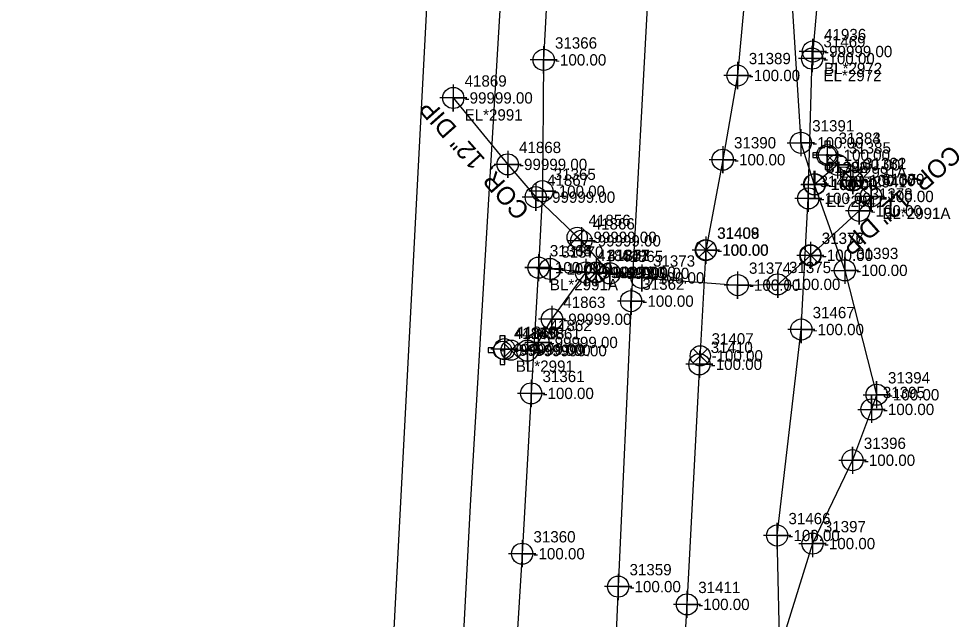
# Model space of a CAD drawing. Extents: x 2083698 to 2094313, y 743246 to 752873.
# Drawn here: x 2093555 to 2093762.7, y 745136.4 to 745269.1 of the extents above; entities that cross this region are included whole.
import ezdxf

# ---------------------------------------------------------------- set-up
doc = ezdxf.new("R2010")
doc.units = 0
for name, color, linetype in [('COGO Default Chain', 7, 'Continuous'), ('COGO Default Curve', 7, 'Continuous'), ('COGO Default Point Number', 7, 'Continuous'), ('Exist Property Line', 7, 'Continuous'), ('Exist Right of Way Easement Line', 7, 'Continuous'), ('Exist Right of Way Easement Line Leader', 7, 'Continuous'), ('Exist Right of Way Easement Line Text', 7, 'Continuous'), ('Exist Right of Way Line', 7, 'Continuous'), ('Exist Right of Way Line Leader', 7, 'Continuous'), ('Exist Right of Way Line Text', 7, 'Continuous'), ('Exist Right of Way Width CELL', 7, 'Continuous'), ('Exist Roads EOP', 7, 'Continuous'), ('Exist Roads EOP Leader', 7, 'Continuous'), ('Exist Roads EOP Text', 7, 'Continuous'), ('Exist Utilities Gas UG Line SUE LOS B', 7, 'Continuous'), ('Exist Utilities Power UG Cable SUE LOS C', 7, 'Continuous'), ('Exist Utilities Telephone UG Conduit SUE LOS B', 7, 'Continuous'), ('Exist Utilities Telephone UG Conduit SUE LOS D', 7, 'Continuous'), ('Exist Utilities Water UG Line SUE LOS B', 7, 'Continuous'), ('Exist Utilities Water UG Line SUE LOS B Text', 7, 'Continuous'), ('Old_Level_20', 7, 'Continuous'), ('Raster_Level_1', 7, 'Continuous'), ('Scratch_Level_2', 7, 'Continuous'), ('Scratch_Level_3', 7, 'Continuous')]:
    doc.layers.add(name, color=color, linetype=linetype)

msp = doc.modelspace()

# ---------------------------------------------------------------- linework, layer by layer
at = {"layer": 'COGO Default Curve'}
for points in [[(2093724.76, 745241.69), (2093730.76, 745241.69), (2093727.76, 745241.69), (2093727.76, 745244.69), (2093727.76, 745238.69)], [(2093732.85, 745236.81), (2093738.85, 745236.81), (2093735.85, 745236.81), (2093735.85, 745239.81), (2093735.85, 745233.81)], [(2093727.72, 745232.48), (2093733.72, 745232.48), (2093730.72, 745232.48), (2093730.72, 745235.48), (2093730.72, 745229.48)], [(2093727.85, 745232.5), (2093733.85, 745232.5), (2093730.85, 745232.5), (2093730.85, 745235.5), (2093730.85, 745229.5)], [(2093734.48, 745213.48), (2093740.48, 745213.48), (2093737.48, 745213.48), (2093737.48, 745216.48), (2093737.48, 745210.48)], [(2093741.49, 745185.98), (2093747.49, 745185.98), (2093744.49, 745185.98), (2093744.49, 745188.98), (2093744.49, 745182.98)], [(2093740.37, 745182.74), (2093746.37, 745182.74), (2093743.37, 745182.74), (2093743.37, 745185.74), (2093743.37, 745179.74)], [(2093736.16, 745171.5), (2093742.16, 745171.5), (2093739.16, 745171.5), (2093739.16, 745174.5), (2093739.16, 745168.5)], [(2093727.33, 745153.07), (2093733.33, 745153.07), (2093730.33, 745153.07), (2093730.33, 745156.07), (2093730.33, 745150.07)]]:
    msp.add_lwpolyline(points, dxfattribs=at)
for centre in [(2093727.76, 745241.69), (2093735.85, 745236.81), (2093730.72, 745232.48), (2093730.85, 745232.5), (2093737.48, 745213.48), (2093744.49, 745185.98), (2093743.37, 745182.74), (2093739.16, 745171.5), (2093730.33, 745153.07)]:
    msp.add_circle(centre, 2.34, dxfattribs=at)
at = {"layer": 'COGO Default Point Number'}
for points in [[(2093670.94, 745263.01), (2093670.94, 745257.01), (2093670.94, 745260.01), (2093673.94, 745260.01), (2093667.94, 745260.01)], [(2093713.75, 745259.56), (2093713.75, 745253.56), (2093713.75, 745256.56), (2093716.75, 745256.56), (2093710.75, 745256.56)], [(2093650.98, 745254.6), (2093650.98, 745248.6), (2093650.98, 745251.6), (2093653.98, 745251.6), (2093647.98, 745251.6)], [(2093733.6, 745241.94), (2093733.6, 745235.94), (2093733.6, 745238.94), (2093736.6, 745238.94), (2093730.6, 745238.94)], [(2093663, 745239.91), (2093663, 745233.91), (2093663, 745236.91), (2093666, 745236.91), (2093660, 745236.91)], [(2093710.49, 745240.94), (2093710.49, 745234.94), (2093710.49, 745237.94), (2093713.49, 745237.94), (2093707.49, 745237.94)], [(2093739.21, 745236.32), (2093739.21, 745230.32), (2093739.21, 745233.32), (2093742.21, 745233.32), (2093736.21, 745233.32)], [(2093670.66, 745233.97), (2093670.66, 745227.97), (2093670.66, 745230.97), (2093673.66, 745230.97), (2093667.66, 745230.97)], [(2093669.19, 745232.67), (2093669.19, 745226.67), (2093669.19, 745229.67), (2093672.19, 745229.67), (2093666.19, 745229.67)], [(2093743.24, 745232.83), (2093743.24, 745226.83), (2093743.24, 745229.83), (2093746.24, 745229.83), (2093740.24, 745229.83)], [(2093743.26, 745232.82), (2093743.26, 745226.82), (2093743.26, 745229.82), (2093746.26, 745229.82), (2093740.26, 745229.82)], [(2093740.64, 745229.63), (2093740.64, 745223.63), (2093740.64, 745226.63), (2093743.64, 745226.63), (2093737.64, 745226.63)], [(2093679.27, 745223.01), (2093679.27, 745217.01), (2093679.27, 745220.01), (2093682.27, 745220.01), (2093676.27, 745220.01)], [(2093706.75, 745220.95), (2093706.75, 745214.95), (2093706.75, 745217.95), (2093709.75, 745217.95), (2093703.75, 745217.95)], [(2093729.86, 745219.8), (2093729.86, 745213.8), (2093729.86, 745216.8), (2093732.86, 745216.8), (2093726.86, 745216.8)], [(2093669.8, 745217.08), (2093669.8, 745211.08), (2093669.8, 745214.08), (2093672.8, 745214.08), (2093666.8, 745214.08)], [(2093669.81, 745217.07), (2093669.81, 745211.07), (2093669.81, 745214.07), (2093672.81, 745214.07), (2093666.81, 745214.07)], [(2093672.35, 745216.79), (2093672.35, 745210.79), (2093672.35, 745213.79), (2093675.35, 745213.79), (2093669.35, 745213.79)], [(2093680.26, 745216.02), (2093680.26, 745210.02), (2093680.26, 745213.02), (2093683.26, 745213.02), (2093677.26, 745213.02)], [(2093682.52, 745216.02), (2093682.52, 745210.02), (2093682.52, 745213.02), (2093685.52, 745213.02), (2093679.52, 745213.02)], [(2093685.55, 745215.82), (2093685.55, 745209.82), (2093685.55, 745212.82), (2093688.55, 745212.82), (2093682.55, 745212.82)], [(2093692.6, 745214.81), (2093692.6, 745208.81), (2093692.6, 745211.81), (2093695.6, 745211.81), (2093689.6, 745211.81)], [(2093713.79, 745213.22), (2093713.79, 745207.22), (2093713.79, 745210.22), (2093716.79, 745210.22), (2093710.79, 745210.22)], [(2093722.64, 745213.38), (2093722.64, 745207.38), (2093722.64, 745210.38), (2093725.64, 745210.38), (2093719.64, 745210.38)], [(2093672.78, 745205.67), (2093672.78, 745199.67), (2093672.78, 745202.67), (2093675.78, 745202.67), (2093669.78, 745202.67)], [(2093669.76, 745200.55), (2093669.76, 745194.55), (2093669.76, 745197.55), (2093672.76, 745197.55), (2093666.76, 745197.55)], [(2093662.29, 745199.05), (2093662.29, 745193.05), (2093662.29, 745196.05), (2093665.29, 745196.05), (2093659.29, 745196.05)], [(2093667.34, 745198.73), (2093667.34, 745192.73), (2093667.34, 745195.73), (2093670.34, 745195.73), (2093664.34, 745195.73)], [(2093705.34, 745195.71), (2093705.34, 745189.71), (2093705.34, 745192.71), (2093708.34, 745192.71), (2093702.34, 745192.71)], [(2093668.19, 745189.28), (2093668.19, 745183.28), (2093668.19, 745186.28), (2093671.19, 745186.28), (2093665.19, 745186.28)], [(2093666.19, 745153.83), (2093666.19, 745147.83), (2093666.19, 745150.83), (2093669.19, 745150.83), (2093663.19, 745150.83)], [(2093702.59, 745142.63), (2093702.59, 745136.63), (2093702.59, 745139.63), (2093705.59, 745139.63), (2093699.59, 745139.63)]]:
    msp.add_lwpolyline(points, dxfattribs=at)
for centre in [(2093670.94, 745260.01), (2093713.75, 745256.56), (2093650.98, 745251.6), (2093710.49, 745237.94), (2093733.6, 745238.94), (2093663, 745236.91), (2093739.21, 745233.32), (2093669.19, 745229.67), (2093670.66, 745230.97), (2093743.24, 745229.83), (2093743.26, 745229.82), (2093740.64, 745226.63), (2093679.27, 745220.01), (2093706.75, 745217.95), (2093729.86, 745216.8), (2093669.8, 745214.08), (2093669.81, 745214.07), (2093672.35, 745213.79), (2093680.26, 745213.02), (2093682.52, 745213.02), (2093685.55, 745212.82), (2093692.6, 745211.81), (2093722.64, 745210.38), (2093713.79, 745210.22), (2093672.78, 745202.67), (2093662.29, 745196.05), (2093667.34, 745195.73), (2093669.76, 745197.55), (2093705.34, 745192.71), (2093668.19, 745186.28), (2093666.19, 745150.83), (2093702.59, 745139.63)]:
    msp.add_circle(centre, 2.34, dxfattribs=at)
at = {"layer": 'Exist Right of Way Line Text'}
for points in [[(2093730.35, 745264.68), (2093730.39, 745258.87), (2093730.37, 745261.87), (2093733.39, 745261.87), (2093727.39, 745261.87)], [(2093730.21, 745263.12), (2093730.24, 745257.3), (2093730.22, 745260.3), (2093733.24, 745260.3), (2093727.24, 745260.3)], [(2093729.36, 745232.2), (2093729.39, 745226.39), (2093729.38, 745229.39), (2093732.39, 745229.39), (2093726.39, 745229.39)], [(2093690.21, 745209.49), (2093690.25, 745203.68), (2093690.23, 745206.68), (2093693.25, 745206.68), (2093687.25, 745206.68)], [(2093727.81, 745203.21), (2093727.85, 745197.4), (2093727.83, 745200.4), (2093730.85, 745200.4), (2093724.85, 745200.4)], [(2093722.48, 745157.68), (2093722.51, 745151.86), (2093722.5, 745154.86), (2093725.51, 745154.86), (2093719.51, 745154.86)], [(2093687.38, 745146.37), (2093687.41, 745140.56), (2093687.39, 745143.56), (2093690.41, 745143.56), (2093684.41, 745143.56)]]:
    msp.add_lwpolyline(points, dxfattribs=at)
for centre in [(2093730.24, 745260.3), (2093730.39, 745261.87), (2093729.39, 745229.39), (2093690.25, 745206.68), (2093727.85, 745200.4), (2093722.51, 745154.86), (2093687.41, 745143.56)]:
    msp.add_circle(centre, 2.34, dxfattribs=at)
at = {"layer": 'Exist Roads EOP'}
for points in [[(2093740.81, 745234.94), (2093737.66, 745231.79), (2093739.24, 745233.36), (2093740.81, 745231.79), (2093737.66, 745234.94)], [(2093679.92, 745222.36), (2093676.77, 745219.21), (2093678.35, 745220.79), (2093679.92, 745219.21), (2093676.77, 745222.36)], [(2093708.4, 745219.55), (2093705.25, 745216.4), (2093706.82, 745217.98), (2093708.4, 745216.4), (2093705.25, 745219.55)], [(2093731.46, 745218.41), (2093728.31, 745215.26), (2093729.88, 745216.83), (2093731.46, 745215.26), (2093728.31, 745218.41)], [(2093684.06, 745214.62), (2093680.91, 745211.47), (2093682.48, 745213.04), (2093684.06, 745211.47), (2093680.91, 745214.62)], [(2093684.15, 745214.63), (2093681, 745211.48), (2093682.57, 745213.06), (2093684.15, 745211.48), (2093681, 745214.63)], [(2093665.31, 745197.4), (2093662.16, 745194.25), (2093663.74, 745195.83), (2093665.31, 745194.25), (2093662.16, 745197.4)], [(2093707.1, 745196.15), (2093703.95, 745193), (2093705.53, 745194.58), (2093707.1, 745193), (2093703.95, 745196.15)]]:
    msp.add_lwpolyline(points, dxfattribs=at)
for centre in [(2093739.24, 745233.36), (2093678.35, 745220.79), (2093706.82, 745217.98), (2093729.88, 745216.83), (2093682.48, 745213.04), (2093682.57, 745213.06), (2093663.74, 745195.83), (2093705.53, 745194.58)]:
    msp.add_circle(centre, 2.23, dxfattribs=at)
at = {"layer": 'Exist Utilities Gas UG Line SUE LOS B'}
msp.add_line((2093735.85, 745236.81), (2093730.85, 745232.5), dxfattribs=at)
msp.add_lwpolyline([(2093725.11, 745283.85), (2093727.76, 745241.69), (2093730.72, 745232.48), (2093737.48, 745213.48), (2093744.49, 745185.98), (2093743.37, 745182.74), (2093739.16, 745171.5), (2093730.33, 745153.07), (2093723.45, 745131.04), (2093716.57, 745100.74), (2093713.22, 745075.27), (2093711.06, 745049.53), (2093708, 745004.83), (2093705.88, 744955.66), (2093705.01, 744921.44), (2093703.7, 744905.03), (2093703.35, 744902.58)], dxfattribs=at)
at = {"layer": 'Exist Utilities Power UG Cable SUE LOS C'}
msp.add_lwpolyline([(2093680.17, 745945.58), (2093662.25, 745598.14), (2093631.4, 745010.86), (2093607.2, 744576.6), (2093577.14, 744030.24)], dxfattribs=at)
at = {"layer": 'Exist Utilities Telephone UG Conduit SUE LOS B'}
for points in [[(2093735.45, 745364.72), (2093733.3, 745337.64), (2093732.44, 745285.39), (2093730.39, 745261.87)], [(2093697.21, 745325.15), (2093694.16, 745278.5), (2093690.25, 745206.68), (2093687.41, 745143.56), (2093686.01, 745111.4), (2093684.05, 745083.9), (2093679.42, 745032.5), (2093678.49, 745004.39), (2093675.74, 744971.19), (2093674.04, 744924.61), (2093672.25, 744890.43), (2093670.38, 744864.8), (2093665.58, 744791.48)], [(2093698.44, 744824.58), (2093701.42, 744845.41), (2093704.79, 744898.66), (2093706.41, 744917.61), (2093708.38, 744951.61), (2093708.96, 744974.75), (2093709.34, 744992.87), (2093712.14, 745012.91), (2093714.5, 745049.5), (2093716.66, 745074.72), (2093723.15, 745125.97), (2093722.51, 745154.86), (2093727.85, 745200.4), (2093729.39, 745229.39), (2093730.24, 745260.3)]]:
    msp.add_lwpolyline(points, dxfattribs=at)
at = {"layer": 'Exist Utilities Telephone UG Conduit SUE LOS D'}
msp.add_lwpolyline([(2093729.86, 746559.98), (2093729.86, 746485.51), (2093728.61, 746416.16), (2093711.62, 746127.01), (2093702.37, 745955.82), (2093693.11, 745784.64), (2093668.68, 745395.41), (2093654.74, 745161.51), (2093649.12, 745054.6), (2093640.35, 744903.62), (2093631.77, 744751.08), (2093623.85, 744627.43), (2093615.93, 744503.79), (2093603.66, 744373.9), (2093590.72, 744165.44), (2093582.98, 744085.27), (2093575.24, 744005.11), (2093571.65, 743852.76), (2093573.5, 743810.29), (2093555.01, 743734.28)], dxfattribs=at)
at = {"layer": 'Exist Utilities Water UG Line SUE LOS B'}
for points in [[(2093673.99, 745318.55), (2093670.94, 745260.01), (2093670.66, 745230.97), (2093669.8, 745214.08), (2093668.7, 745195.16)], [(2093717.06, 745292.6), (2093713.75, 745256.56), (2093710.49, 745237.94), (2093706.75, 745217.95), (2093705.34, 745192.71), (2093702.59, 745139.63), (2093699.85, 745093.49), (2093696.94, 745031.83), (2093696.13, 745005.41), (2093692.66, 744951.33), (2093690.44, 744916.98), (2093684.85, 744862.65), (2093681.73, 744819.13)], [(2093650.98, 745251.6), (2093663, 745236.91), (2093669.19, 745229.67), (2093679.27, 745220.01), (2093685.55, 745212.82), (2093684.68, 745212.85)], [(2093743.24, 745229.83), (2093739.21, 745233.32), (2093733.6, 745238.94)], [(2093669.81, 745214.07), (2093672.35, 745213.79), (2093682.52, 745213.02), (2093692.6, 745211.81), (2093713.79, 745210.22), (2093722.64, 745210.38), (2093729.86, 745216.8), (2093740.64, 745226.63), (2093743.26, 745229.82)], [(2093667.34, 745195.73), (2093669.76, 745197.55), (2093672.78, 745202.67), (2093680.26, 745213.02), (2093681.64, 745212.96)], [(2093684.68, 745212.85), (2093681.64, 745212.96)], [(2093662.29, 745196.05), (2093667.34, 745195.73)], [(2093668.7, 745195.16), (2093668.19, 745186.28), (2093666.19, 745150.83), (2093662.2, 745086.66), (2093659.93, 745032.57), (2093656.37, 744981.33), (2093656.4, 744957.87), (2093654.11, 744908.82), (2093650.64, 744851.04), (2093647.89, 744799.14)]]:
    msp.add_lwpolyline(points, dxfattribs=at)
at = {"layer": 'Raster_Level_1'}
for p, q in [((2093733.6, 745238.95), (2093733.6, 745238.95)), ((2093661.87, 745195.84), (2093661.87, 745195.84))]:
    msp.add_line(p, q, dxfattribs=at)
for points in [[(2093733.09, 745240.86), (2093733.09, 745242.15), (2093734.12, 745242.15), (2093734.12, 745240.84)], [(2093731.69, 745239.46), (2093730.4, 745239.46), (2093730.4, 745238.44), (2093731.69, 745238.44)], [(2093733.09, 745237.04), (2093733.09, 745235.75), (2093734.12, 745235.75), (2093734.12, 745237.06)], [(2093661.36, 745197.76), (2093661.36, 745199.05), (2093662.38, 745199.05), (2093662.38, 745197.73)], [(2093659.96, 745196.36), (2093658.67, 745196.36), (2093658.67, 745195.33), (2093659.96, 745195.33)], [(2093661.36, 745193.93), (2093661.36, 745192.65), (2093662.38, 745192.65), (2093662.38, 745193.96)]]:
    msp.add_lwpolyline(points, dxfattribs=at)
for centre, radius in [((2093733.6, 745238.95), 1.98), ((2093733.6, 745238.95), 0.243), ((2093661.87, 745195.84), 1.98), ((2093661.87, 745195.84), 0.243)]:
    msp.add_circle(centre, radius, dxfattribs=at)

# ---------------------------------------------------------------- texts
at = {"layer": 'COGO Default Chain'}
for p in [(2093730.26, 745240.44), (2093738.35, 745235.56), (2093733.22, 745231.23), (2093733.35, 745231.25), (2093739.98, 745212.23), (2093746.99, 745184.73), (2093745.87, 745181.49), (2093741.66, 745170.25), (2093732.83, 745151.82)]:
    msp.add_text('-100.00', height=2.5, dxfattribs=at).set_placement(p)
at = {"layer": 'Exist Property Line'}
for s, p in [('-100.00', (2093673.44, 745258.76)), ('-100.00', (2093716.25, 745255.31)), ('-99999.00', (2093653.48, 745250.35)), ('-100.00', (2093736.1, 745237.69)), ('-99999.00', (2093665.5, 745235.66)), ('-100.00', (2093712.99, 745236.69)), ('-100.00', (2093741.71, 745232.07)), ('-100.00', (2093673.16, 745229.72)), ('-99999.00', (2093671.69, 745228.42)), ('-100.00', (2093745.74, 745228.58)), ('-100.00', (2093745.76, 745228.57)), ('-100.00', (2093743.14, 745225.38)), ('-99999.00', (2093681.77, 745218.76)), ('-100.00', (2093709.25, 745216.7)), ('-100.00', (2093732.36, 745215.55)), ('-100.00', (2093672.3, 745212.83)), ('-100.00', (2093672.31, 745212.82)), ('-100.00', (2093674.85, 745212.54)), ('-99999.00', (2093682.76, 745211.77)), ('-100.00', (2093685.02, 745211.77)), ('-99999.00', (2093688.05, 745211.57)), ('-100.00', (2093695.1, 745210.56)), ('-100.00', (2093716.29, 745208.97)), ('-100.00', (2093725.14, 745209.13)), ('-99999.00', (2093675.28, 745201.42)), ('-99999.00', (2093672.26, 745196.3)), ('-99999.00', (2093664.79, 745194.8)), ('-99999.00', (2093669.84, 745194.48)), ('-100.00', (2093707.84, 745191.46)), ('-100.00', (2093670.69, 745185.03)), ('-100.00', (2093668.69, 745149.58)), ('-100.00', (2093705.09, 745138.38))]:
    msp.add_text(s, height=2.5, dxfattribs=at).set_placement(p)
at = {"layer": 'Exist Right of Way Easement Line'}
for s, p in [('BL*2941', (2093738.35, 745231.81)), ('EL*2941', (2093733.35, 745227.5))]:
    msp.add_text(s, height=2.5, dxfattribs=at).set_placement(p)
at = {"layer": 'Exist Right of Way Easement Line Leader'}
for s, p in [('-100.00', (2093736.1, 745237.7)), ('-99999.00', (2093664.37, 745194.59))]:
    msp.add_text(s, height=2.5, dxfattribs=at).set_placement(p)
at = {"layer": 'Exist Right of Way Easement Line Text'}
for s, p in [('31383', (2093736.1, 745241.45)), ('41859', (2093664.37, 745198.34))]:
    msp.add_text(s, height=2.5, dxfattribs=at).set_placement(p)
at = {"layer": 'Exist Right of Way Line'}
for s, p in [('31366', (2093673.44, 745262.51)), ('31389', (2093716.25, 745259.06)), ('41869', (2093653.48, 745254.1)), ('31384', (2093736.1, 745241.44)), ('41868', (2093665.5, 745239.41)), ('31390', (2093712.99, 745240.44)), ('31381', (2093741.71, 745235.82)), ('31365', (2093673.16, 745233.47)), ('41867', (2093671.69, 745232.17)), ('31380', (2093745.74, 745232.33)), ('31379', (2093745.76, 745232.32)), ('31378', (2093743.14, 745229.13)), ('41866', (2093681.77, 745222.51)), ('31409', (2093709.25, 745220.45)), ('31377', (2093732.36, 745219.3)), ('31363', (2093672.3, 745216.58)), ('31364', (2093672.31, 745216.57)), ('31370', (2093674.85, 745216.29)), ('41864', (2093682.76, 745215.52)), ('31372', (2093685.02, 745215.52)), ('41865', (2093688.05, 745215.32)), ('31373', (2093695.1, 745214.31)), ('31374', (2093716.29, 745212.72)), ('31375', (2093725.14, 745212.88)), ('41863', (2093675.28, 745205.17)), ('41862', (2093672.26, 745200.05)), ('41860', (2093664.79, 745198.55)), ('41861', (2093669.84, 745198.23)), ('31410', (2093707.84, 745195.21)), ('31361', (2093670.69, 745188.78)), ('31360', (2093668.69, 745153.33)), ('31411', (2093705.09, 745142.13))]:
    msp.add_text(s, height=2.5, dxfattribs=at).set_placement(p)
at = {"layer": 'Exist Right of Way Line Leader'}
for s, p in [('41936', (2093732.89, 745264.37)), ('31469', (2093732.74, 745262.8)), ('31468', (2093731.89, 745231.89)), ('31362', (2093692.75, 745209.18)), ('31467', (2093730.35, 745202.9)), ('31466', (2093725.01, 745157.36)), ('31359', (2093689.91, 745146.06))]:
    msp.add_text(s, height=2.5, dxfattribs=at).set_placement(p)
at = {"layer": 'Exist Right of Way Width CELL'}
for s, p in [('EL*2991', (2093653.48, 745246.6)), ('EL*2991A', (2093736.1, 745233.94)), ('BL*2991A', (2093745.74, 745224.83)), ('EL*2991A', (2093745.76, 745224.82)), ('BL*2991A', (2093672.31, 745209.07)), ('BL*2991', (2093664.79, 745191.05))]:
    msp.add_text(s, height=2.5, dxfattribs=at).set_placement(p)
at = {"layer": 'Exist Roads EOP Leader'}
for s, p in [('-100.00', (2093741.74, 745232.11)), ('-99999.00', (2093680.85, 745219.54)), ('-100.00', (2093709.32, 745216.73)), ('-100.00', (2093732.38, 745215.58)), ('-100.00', (2093684.98, 745211.79)), ('-99999.00', (2093685.07, 745211.81)), ('-99999.00', (2093666.24, 745194.58)), ('-100.00', (2093708.03, 745193.33))]:
    msp.add_text(s, height=2.5, dxfattribs=at).set_placement(p)
at = {"layer": 'Exist Roads EOP Text'}
for s, p in [('31382', (2093741.74, 745235.86)), ('41856', (2093680.85, 745223.29)), ('31408', (2093709.32, 745220.48)), ('31376', (2093732.38, 745219.33)), ('31371', (2093684.98, 745215.54)), ('41857', (2093685.07, 745215.56)), ('41858', (2093666.24, 745198.33)), ('31407', (2093708.03, 745197.08))]:
    msp.add_text(s, height=2.5, dxfattribs=at).set_placement(p)
at = {"layer": 'Exist Utilities Water UG Line SUE LOS B Text'}
for rotation, p in [(131.6228, (2093668.07, 745226.88)), (221.6228, (2093760.94, 745241.46))]:
    msp.add_text('COR, 12" DIP', height=4, rotation=rotation, dxfattribs=at).set_placement(p)
at = {"layer": 'Old_Level_20'}
for s, p in [('31391', (2093730.26, 745244.19)), ('31385', (2093738.35, 745239.31)), ('31392', (2093733.22, 745234.98)), ('31386', (2093733.35, 745235)), ('31393', (2093739.98, 745215.98)), ('31394', (2093746.99, 745188.48)), ('31395', (2093745.87, 745185.24)), ('31396', (2093741.66, 745174)), ('31397', (2093732.83, 745155.57))]:
    msp.add_text(s, height=2.5, dxfattribs=at).set_placement(p)
at = {"layer": 'Scratch_Level_2'}
for s, p in [('-99999.00', (2093732.89, 745260.62)), ('-100.00', (2093732.74, 745259.05)), ('-100.00', (2093731.89, 745228.14)), ('-100.00', (2093692.75, 745205.43)), ('-100.00', (2093730.35, 745199.15)), ('-100.00', (2093725.01, 745153.61)), ('-100.00', (2093689.91, 745142.31))]:
    msp.add_text(s, height=2.5, dxfattribs=at).set_placement(p)
at = {"layer": 'Scratch_Level_3'}
for s, p in [('BL*2972', (2093732.89, 745256.87)), ('EL*2972', (2093732.74, 745255.3))]:
    msp.add_text(s, height=2.5, dxfattribs=at).set_placement(p)

doc.saveas('drawing.dxf')
